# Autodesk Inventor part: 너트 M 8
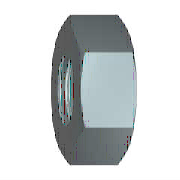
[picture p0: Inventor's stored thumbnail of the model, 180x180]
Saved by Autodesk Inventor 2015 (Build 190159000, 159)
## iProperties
IsCustomPart: 1
Created: 2012-02
Part Number: 너트 M 8
Material: 강철, 연강
Description: 6각 너트 및 6각 가는 너트
Document SubType Name: Modeling
Standard: KS B 1012
Designer: mduedu
Standards Organization: KS
Language: ko-KR
Size Designation: M 8
Categories: <MemberInstance><Categories><Category DisplayName="조임쇠" InternalName="e4da775c-781d-43d5-af7c-5136215cf5a6" Mnemonic="FSTN"><Category DisplayName="너트" InternalN
Density: 1 g/cm^3
Appearance: 강철
Author: mduedu
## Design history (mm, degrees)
sketch "스케치1"
  geometry: L1 (-7.506, 0)-(-3.753, 6.5); L2 (-3.753, 6.5)-(3.753, 6.5); L3 (3.753, 6.5)-(7.506, 0); L4 (7.506, 0)-(3.753, -6.5); L5 (3.753, -6.5)-(-3.753, -6.5); L6 (-3.753, -6.5)-(-7.506, 0); 2 further points
  constraints: 12 end point, 1 coincident, 1 horizontal, 11 other
  dimensions: "d0" = 15.01111 distance of L3.end L1.start (= 1.1547 x SW)
extrude "본체" new body sketch "스케치1" distance "d1" = 5 (= KOH); taper "d2" = 0 deg
sketch "스케치2"
  geometry: L1 (0, 3.753)-(0, 7.506) reference; L2 (0, 7.506)-(5, 7.506) reference; L3 (5, 3.753)-(5, 7.506) reference; L4 (-1, 0)-(6, 0) reference; L5 (0.581, 7.506)-(0, 6.5); L6 (4.419, 7.506)-(5, 6.5)
  constraints: 4 end point, 4 point on line
  dimensions: "d3" = 30 deg angle of L1 L5 (= ANG1); "d4" = 30 deg angle of L3 L6 (= ANG2); "d5" = 13 diameter of L5.end L4 (= SW0); "d6" = 13 diameter of L6.end L4 (= SW01)
revolve "모따기1" sketch "스케치2" stored, may be unused: angle "d7" = 90 deg
sketch "스케치3"
  geometry: A1 r 6.5 centre (0, 0) between (-3.25, -5.629) and (3.25, -5.629) reference; 1 further point
  constraints: 1 coincident
hole "스레드" sketch "스케치3" at (0, 0) diameter "d25" = 6.647; stored, may be unused: countersink angle "d29" = 82 deg, drill point angle "d31" = 118 deg; dims "d26" = 6, "d27" = 4, "d28" = 2, "d30" = 8
workaxis "Work Axis1"
workplane "Work Plane1"
body "Solid1"
chamfer "모따기2" distance "d8" = 0.67658 (= -0.5 x GD1 + 0.5 x NND); stored, may be unused: angle "d9" = 30 deg, second distance "d40" = 0.67658 (= -0.5 x GD1 + 0.5 x NND)
chamfer "모따기3" distance "d10" = 0.67658 (= -0.5 x GD1 + 0.5 x NND); stored, may be unused: angle "d11" = 30 deg, second distance "d41" = 0.67658 (= -0.5 x GD1 + 0.5 x NND)
other parameters: "ANG1" = 30 deg [user parameter; used in 1 equation term], "ANG2" = 30 deg [user parameter; used in 1 equation term], "NND" = 8 [user parameter; used in 4 equation terms], "KOH" = 5 [user parameter; used in 1 equation term], "SW" = 13 [user parameter; used in 4 equation terms], "SW0" = 13 (= SW) [user parameter; used in 1 equation term], "SW01" = 13 (= SW) [user parameter; used in 1 equation term], "GD1" = 6.64684 (computed from THREADDIA, PTC, TOA) [user parameter; used in 4 equation terms], "d13" = 0, "d14" = 0, "d39" = 0, "d42" = 0, "GUL" = 0.67658 (= 0.541266 x PTC) [user parameter], "TPU" = 8 (computed from PTC) [user parameter], "THREADDIA" = 8 [user parameter; used in 1 equation term], "TOA" = 30 deg [user parameter; used in 1 equation term], "PTC" = 1.25 [user parameter; used in 4 equation terms], "E0" = 15.015 (= 1.155 x SW) [user parameter], "GAL" = 0.67658 (= 0.541266 x PTC) [user parameter]
